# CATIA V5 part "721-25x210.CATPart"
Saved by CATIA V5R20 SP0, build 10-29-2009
Part number: 721-25x210
Definition: NONE
Nomenclature: 721-25x210
Source: Unknown
Description: 721-25x210
Bounding box of the stored display mesh (mm): x -90 to 120, y -24 to 24, z -24 to 24
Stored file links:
  C:\Users\Utente\Desktop\IO LAVORO\3D X SITO CF\X SITO\721\721-25x210.CATPart
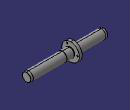
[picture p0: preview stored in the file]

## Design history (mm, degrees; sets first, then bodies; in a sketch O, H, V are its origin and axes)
Body1 "721-25x210" (main body)
  Solid1: solid without history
